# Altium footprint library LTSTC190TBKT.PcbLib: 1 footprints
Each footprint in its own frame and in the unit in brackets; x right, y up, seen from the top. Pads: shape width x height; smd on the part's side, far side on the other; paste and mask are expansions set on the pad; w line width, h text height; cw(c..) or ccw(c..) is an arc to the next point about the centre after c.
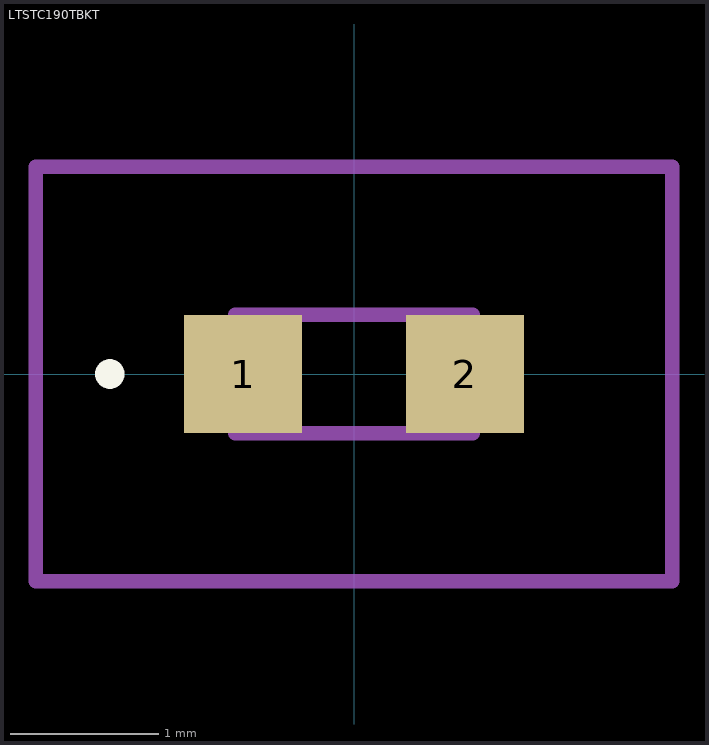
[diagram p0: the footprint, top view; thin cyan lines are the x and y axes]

## LTSTC190TBKT [mm]
pads (2):
  rect 0.8x0.8 smd: 1(-0.75,0) 2(0.75,0)
Top Overlay:
  lines w0.1: -1.7,0 cw(c-1.65,0) -1.6,0 ; -1.7,0 -1.7,0 ; -1.7,0 ccw(c-1.65,0) -1.6,0 ; -1.6,0 -1.6,0
Mechanical 15:
  lines w0.1: -0.8,-0.4 0.8,-0.4 0.8,0.4 -0.8,0.4 -0.8,-0.4
Mechanical 20:
  lines w0.1: -2.15,-1.4 2.15,-1.4 2.15,1.4 -2.15,1.4 -2.15,-1.4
